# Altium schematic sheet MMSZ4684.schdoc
size 127 x 101 mm
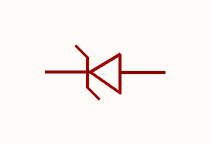
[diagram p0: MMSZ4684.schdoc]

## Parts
ZD?  mmsz4684  [SOD-123_L2.8-W1.8-LS3.7-RD]  (value not drawn)

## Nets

Not connected (* = marked no-connect by the designer): ZD? 1(K) 2(A)

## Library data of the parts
ZD? = mmsz4684: 二极管配置:1个独立式;稳压值(标称值):3.3V;稳压值(范围):3.13V~3.47V;耗散功率(Pd):350mW;; Manufacturer: CJ(江苏长电/长晶); AddInBom: yes; ModelId: 7884390a25fb4c08947731ebfba7e3f8; ModelTransform: 144.8816,62.992,0,0,0,0,0,0,0; Diode Configuration: 1个独立式; Zener Voltage(Nom): 3.3V; Reverse Leakage Current (Ir): 7.5uA; Pd - Power Dissipation: 350mW; Operating Junction Temperature Range: -65℃~+150℃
